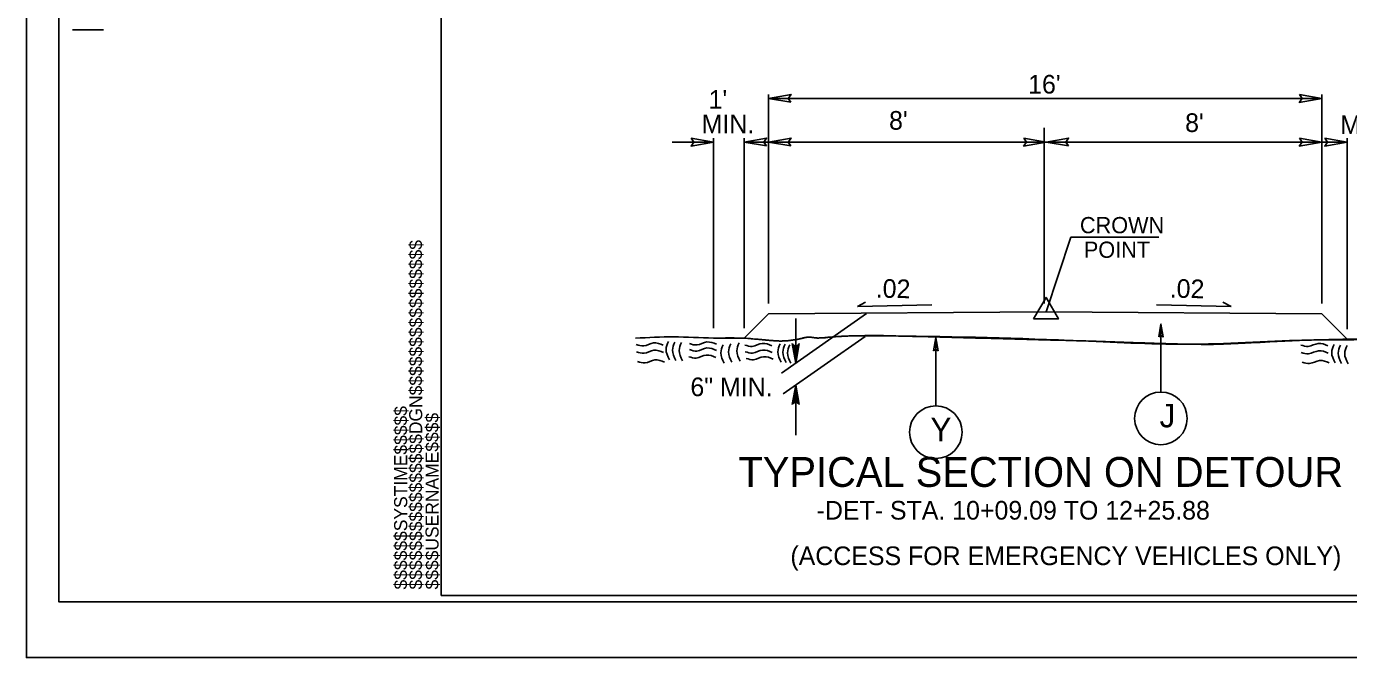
# Model space of a CAD drawing. Extents: x 575722 to 576066, y -53107 to -52774.
# Drawn here: x 575797.4 to 575850.6, y -53106.9 to -53081.5 of the extents above; entities that cross this region are included whole.
import ezdxf

# ---------------------------------------------------------------- set-up
doc = ezdxf.new("R2010")
doc.units = 0
for name, color, linetype in [('Old_Level_1', 7, 'Continuous'), ('Old_Level_11', 7, 'Continuous'), ('Old_Level_2', 7, 'Continuous'), ('Prop DSN Text', 7, 'Continuous'), ('Prop ROW Marker CELL', 7, 'Continuous'), ('Sheet Cutting Line CELL', 7, 'Continuous'), ('Sheet Plot Border Inside CELL', 7, 'Continuous'), ('Sheet Plot Border Outside CELL', 7, 'Continuous'), ('Sheet Typical CELL', 7, 'Continuous'), ('Typical Grade Point Symbol CELL', 7, 'Continuous'), ('Typical ID Circle CELL', 7, 'Continuous'), ('Typical Pavement Slope CELL', 7, 'Continuous'), ('Typical Terminator CELL', 7, 'Continuous'), ('Typical Text Grade Point CELL', 7, 'Continuous'), ('Typical Text ID Circle CELL', 7, 'Continuous')]:
    doc.layers.add(name, color=color, linetype=linetype)

msp = doc.modelspace()

# ---------------------------------------------------------------- linework, layer by layer
at = {"layer": 'Old_Level_11'}
for p, q in [((575827.258, -53092.635), (575827.258, -53084.22)), ((575849.531, -53092.635), (575849.531, -53084.22)), ((575849.531, -53084.38), (575827.258, -53084.38)), ((575838.357, -53092.635), (575838.357, -53085.564)), ((575825.044, -53086.137), (575823.379, -53086.137)), ((575825.044, -53093.617), (575825.044, -53085.977)), ((575826.273, -53093.624), (575826.273, -53085.977)), ((575827.258, -53086.137), (575826.273, -53086.137)), ((575838.357, -53086.137), (575827.258, -53086.137)), ((575849.531, -53086.137), (575838.357, -53086.137)), ((575850.555, -53086.137), (575849.531, -53086.137)), ((575850.555, -53093.663), (575850.555, -53085.977))]:
    msp.add_line(p, q, dxfattribs=at)
for points in [[(575828.158, -53084.535), (575827.258, -53084.38), (575828.163, -53084.22), (575828.048, -53084.38)], [(575848.631, -53084.225), (575849.531, -53084.38), (575848.626, -53084.54), (575848.741, -53084.38)], [(575824.144, -53085.982), (575825.044, -53086.137), (575824.139, -53086.297), (575824.254, -53086.137)], [(575827.173, -53086.292), (575826.273, -53086.137), (575827.178, -53085.977), (575827.063, -53086.137)], [(575828.158, -53086.292), (575827.258, -53086.137), (575828.163, -53085.977), (575828.048, -53086.137)], [(575837.531, -53085.982), (575838.431, -53086.137), (575837.526, -53086.297), (575837.641, -53086.137)], [(575839.331, -53086.292), (575838.431, -53086.137), (575839.336, -53085.977), (575839.221, -53086.137)], [(575848.631, -53085.982), (575849.531, -53086.137), (575848.626, -53086.297), (575848.741, -53086.137)], [(575849.655, -53085.982), (575850.555, -53086.137), (575849.65, -53086.297), (575849.765, -53086.137)]]:
    msp.add_lwpolyline(points, close=True, dxfattribs=at)
at = {"layer": 'Old_Level_2'}
for points in [[(575855.112, -53093.968), (575854.703, -53093.989), (575853.632, -53093.941), (575852.526, -53094.014), (575849.124, -53094.098), (575844.384, -53094.267), (575839.88, -53094.132), (575832.25, -53093.93), (575830.77, -53093.928), (575830.012, -53093.961), (575829.277, -53094.016), (575829.167, -53094.013), (575829.057, -53093.998), (575828.948, -53093.984), (575828.838, -53093.983), (575828.716, -53094.002), (575828.596, -53094.03), (575828.476, -53094.06), (575828.355, -53094.082), (575827.8, -53094.137), (575827.68, -53094.137), (575827.26, -53094.109), (575826.84, -53094.068), (575826, -53094.017), (575825.044, -53094.017), (575823.437, -53093.971), (575821.903, -53094.025)], [(575823.019, -53094.306), (575822.629, -53094.212), (575822.226, -53094.333), (575821.93, -53094.279)], [(575823.227, -53094.152), (575823.133, -53094.474), (575823.268, -53094.891)], [(575823.483, -53094.178), (575823.389, -53094.501), (575823.523, -53094.918)], [(575823.752, -53094.192), (575823.657, -53094.514), (575823.792, -53094.931)], [(575825.169, -53094.27), (575824.78, -53094.176), (575824.376, -53094.297), (575824.081, -53094.243)], [(575825.43, -53094.29), (575825.336, -53094.613), (575825.47, -53095.03)], [(575825.739, -53094.25), (575825.645, -53094.572), (575825.78, -53094.989)], [(575826.075, -53094.21), (575825.981, -53094.532), (575826.116, -53094.949)], [(575827.395, -53094.325), (575827.005, -53094.231), (575826.602, -53094.352), (575826.306, -53094.298)], [(575827.724, -53094.249), (575827.63, -53094.572), (575827.765, -53094.989)], [(575827.926, -53094.263), (575827.832, -53094.585), (575827.966, -53095.002)], [(575828.114, -53094.29), (575828.02, -53094.612), (575828.154, -53095.029)], [(575849.781, -53094.328), (575849.392, -53094.234), (575848.988, -53094.355), (575848.693, -53094.301)], [(575850.027, -53094.274), (575849.933, -53094.596), (575850.068, -53095.013)], [(575850.283, -53094.301), (575850.189, -53094.623), (575850.323, -53095.04)], [(575850.552, -53094.314), (575850.457, -53094.637), (575850.592, -53095.054)], [(575823.032, -53094.602), (575822.643, -53094.508), (575822.239, -53094.629), (575821.944, -53094.575)], [(575825.142, -53094.794), (575824.753, -53094.7), (575824.35, -53094.821), (575824.054, -53094.767)], [(575825.169, -53094.512), (575824.78, -53094.418), (575824.376, -53094.539), (575824.081, -53094.485)], [(575827.408, -53094.594), (575827.018, -53094.5), (575826.615, -53094.621), (575826.319, -53094.567)], [(575827.448, -53094.863), (575827.059, -53094.769), (575826.655, -53094.889), (575826.36, -53094.836)], [(575849.795, -53094.624), (575849.405, -53094.53), (575849.002, -53094.651), (575848.706, -53094.597)], [(575823.073, -53094.992), (575822.683, -53094.898), (575822.28, -53095.019), (575821.984, -53094.965)], [(575849.835, -53095.014), (575849.445, -53094.92), (575849.042, -53095.041), (575848.746, -53094.987)]]:
    msp.add_spline(points, degree=3, dxfattribs=at)
at = {"layer": 'Prop DSN Text'}
for p, q in [((575831.198, -53093.035), (575827.78, -53095.429)), ((575828.353, -53093.233), (575828.353, -53095.028)), ((575831.146, -53093.951), (575827.845, -53096.263)), ((575828.353, -53095.028), (575828.214, -53094.241)), ((575828.353, -53095.028), (575828.234, -53094.256)), ((575828.253, -53094.271), (575828.353, -53095.028)), ((575828.353, -53095.028), (575828.273, -53094.284)), ((575828.294, -53094.299), (575828.353, -53095.028)), ((575828.353, -53095.028), (575828.313, -53094.314)), ((575828.333, -53094.329), (575828.353, -53095.028)), ((575828.353, -53095.028), (575828.493, -53094.241)), ((575828.473, -53094.256), (575828.353, -53095.028)), ((575828.353, -53095.028), (575828.451, -53094.271)), ((575828.431, -53094.284), (575828.353, -53095.028)), ((575828.353, -53095.028), (575828.412, -53094.299)), ((575828.392, -53094.314), (575828.353, -53095.028)), ((575828.353, -53095.028), (575828.372, -53094.329)), ((575828.353, -53094.343), (575828.353, -53095.028)), ((575828.353, -53095.908), (575828.214, -53096.695)), ((575828.234, -53096.68), (575828.353, -53095.908)), ((575828.353, -53095.908), (575828.253, -53096.666)), ((575828.273, -53096.65), (575828.353, -53095.908)), ((575828.353, -53095.908), (575828.294, -53096.636)), ((575828.313, -53096.623), (575828.353, -53095.908)), ((575828.353, -53095.908), (575828.333, -53096.608)), ((575828.353, -53095.908), (575828.353, -53097.929)), ((575828.353, -53095.908), (575828.493, -53096.695)), ((575828.353, -53096.593), (575828.353, -53095.908)), ((575828.372, -53096.608), (575828.353, -53095.908)), ((575828.353, -53095.908), (575828.392, -53096.623)), ((575828.412, -53096.636), (575828.353, -53095.908)), ((575828.353, -53095.908), (575828.431, -53096.65)), ((575828.451, -53096.666), (575828.353, -53095.908)), ((575828.353, -53095.908), (575828.473, -53096.68))]:
    msp.add_line(p, q, dxfattribs=at)
msp.add_open_spline([(575851.784, -53094.032), (575850.897, -53094.054), (575850.01, -53094.076), (575849.124, -53094.098), (575848.729, -53094.108), (575848.334, -53094.127), (575847.939, -53094.144), (575847.544, -53094.161), (575847.149, -53094.187), (575846.754, -53094.205), (575845.964, -53094.242), (575845.174, -53094.279), (575844.384, -53094.267), (575843.634, -53094.255), (575842.883, -53094.231), (575842.132, -53094.207), (575841.381, -53094.182), (575840.631, -53094.153), (575839.88, -53094.132), (575838.609, -53094.096), (575837.337, -53094.063), (575836.065, -53094.029), (575834.793, -53093.994), (575833.522, -53093.962), (575832.25, -53093.93), (575831.757, -53093.918), (575831.263, -53093.919), (575830.77, -53093.928), (575830.517, -53093.933), (575830.265, -53093.948), (575830.012, -53093.961), (575829.767, -53093.974), (575829.522, -53094.004), (575829.277, -53094.016), (575829.24, -53094.018), (575829.204, -53094.017), (575829.167, -53094.013), (575829.131, -53094.008), (575829.094, -53094.003), (575829.057, -53093.998), (575829.021, -53093.993), (575828.984, -53093.988), (575828.948, -53093.984), (575828.911, -53093.98), (575828.874, -53093.98), (575828.838, -53093.983), (575828.797, -53093.987), (575828.756, -53093.993), (575828.716, -53094.002), (575828.676, -53094.011), (575828.636, -53094.021), (575828.596, -53094.03), (575828.556, -53094.04), (575828.516, -53094.05), (575828.476, -53094.06), (575828.436, -53094.069), (575828.396, -53094.076), (575828.355, -53094.082), (575828.171, -53094.11), (575827.986, -53094.129), (575827.8, -53094.137), (575827.76, -53094.139), (575827.72, -53094.139), (575827.68, -53094.137), (575827.54, -53094.13), (575827.4, -53094.121), (575827.26, -53094.109), (575827.12, -53094.096), (575826.981, -53094.08), (575826.84, -53094.068), (575826.561, -53094.045), (575826.281, -53094.017), (575826, -53094.017), (575825.681, -53094.017), (575825.362, -53094.017), (575825.044, -53094.017)], degree=3, dxfattribs=at)
at = {"layer": 'Prop ROW Marker CELL'}
msp.add_line((575838.431, -53092.959), (575838.431, -53092.959), dxfattribs=at)
msp.add_lwpolyline([(575837.931, -53093.247), (575838.431, -53092.383), (575838.931, -53093.247)], close=True, dxfattribs=at)
at = {"layer": 'Sheet Cutting Line CELL'}
for p, q in [((575797.38, -52996.867), (575797.38, -53106.867)), ((575797.38, -53106.867), (575965.78, -53106.867))]:
    msp.add_line(p, q, dxfattribs=at)
at = {"layer": 'Sheet Plot Border Inside CELL'}
msp.add_lwpolyline([(575965.33, -52999.112), (575798.68, -52999.112), (575798.68, -53104.622), (575965.33, -53104.622)], close=True, dxfattribs=at)
at = {"layer": 'Sheet Plot Border Outside CELL'}
msp.add_lwpolyline([(575965.78, -52996.867), (575797.38, -52996.867), (575797.38, -53106.867), (575965.78, -53106.867)], close=True, dxfattribs=at)
at = {"layer": 'Sheet Typical CELL'}
for p, q in [((575799.23, -53081.617), (575800.48, -53081.617)), ((575814.08, -53104.367), (575814.08, -53104.367)), ((575814.08, -53104.367), (575814.08, -53104.367)), ((575814.08, -53104.367), (575814.08, -53104.367)), ((575814.08, -53104.367), (575814.08, -53104.367)), ((575814.08, -53104.367), (575814.08, -53104.367)), ((575814.08, -53104.367), (575814.08, -53104.367))]:
    msp.add_line(p, q, dxfattribs=at)
msp.add_lwpolyline([(575964.08, -52999.367), (575814.08, -52999.367), (575814.08, -53104.367), (575964.08, -53104.367)], close=True, dxfattribs=at)
msp.add_lwpolyline([(575817.83, -53104.367), (575817.83, -53104.367)], dxfattribs=at)
at = {"layer": 'Typical Grade Point Symbol CELL'}
msp.add_line((575838.431, -53092.959), (575839.431, -53089.959), dxfattribs=at)
at = {"layer": 'Typical ID Circle CELL'}
for p, q in [((575843.054, -53096.19), (575843.054, -53093.456)), ((575833.994, -53096.746), (575833.994, -53094.012))]:
    msp.add_line(p, q, dxfattribs=at)
for centre in [(575843.054, -53097.248), (575833.994, -53097.804)]:
    msp.add_circle(centre, 1.058, dxfattribs=at)
at = {"layer": 'Typical Pavement Slope CELL'}
for p, q in [((575830.834, -53092.744), (575831.167, -53092.578)), ((575833.834, -53092.682), (575830.834, -53092.744)), ((575842.881, -53092.681), (575845.881, -53092.744)), ((575845.881, -53092.744), (575845.548, -53092.577)), ((575827.258, -53093.039), (575826.273, -53094.024)), ((575849.531, -53093.039), (575850.555, -53094.063))]:
    msp.add_line(p, q, dxfattribs=at)
msp.add_lwpolyline([(575827.258, -53093.039), (575838.431, -53092.959), (575849.531, -53093.039)], dxfattribs=at)
at = {"layer": 'Typical Terminator CELL'}
for points in [[(575842.966, -53093.972), (575843.054, -53093.456), (575843.146, -53093.975), (575843.054, -53093.909)], [(575833.905, -53094.528), (575833.994, -53094.012), (575834.086, -53094.531), (575833.994, -53094.465)]]:
    msp.add_lwpolyline(points, close=True, dxfattribs=at)
at = {"layer": 'Typical Text Grade Point CELL'}
msp.add_line((575839.431, -53089.959), (575842.969, -53089.959), dxfattribs=at)

# ---------------------------------------------------------------- texts
at = {"layer": 'Old_Level_1'}
for p in [(575831.568, -53092.389), (575843.404, -53092.391)]:
    msp.add_text('.02', height=0.75, rotation=358.8084, dxfattribs=at).set_placement(p)
at = {"layer": 'Old_Level_11'}
for s, p in [("16'", (575837.71, -53084.185)), (" 1'", (575824.566, -53084.797)), ('MIN.', (575824.566, -53085.78)), ("8'", (575832.11, -53085.639)), ("8'", (575844.03, -53085.731)), ('MIN.', (575850.273, -53085.816))]:
    msp.add_text(s, height=0.75, rotation=360, dxfattribs=at).set_placement(p)
at = {"layer": 'Prop DSN Text'}
for s, p in [('6" MIN.', (575824.112, -53096.356)), ('-DET- STA. 10+09.09 TO 12+25.88', (575829.194, -53101.319)), ('(ACCESS FOR EMERGENCY VEHICLES ONLY)', (575828.138, -53103.15))]:
    msp.add_text(s, height=0.75, dxfattribs=at).set_placement(p)
at = {"layer": 'Sheet Typical CELL'}
for s, p in [('$$$$$$$$$$$$$$$$DGN$$$$$$$$$$$$$$$$', (575813.315, -53104.13)), ('$$$$$$SYSTIME$$$$$', (575812.71, -53104.13)), ('$$$$USERNAME$$$$', (575813.973, -53104.129))]:
    msp.add_text(s, height=0.525, rotation=90, dxfattribs=at).set_placement(p)
at = {"layer": 'Typical Pavement Slope CELL'}
msp.add_text('TYPICAL SECTION ON DETOUR', height=1.2, dxfattribs=at).set_placement((575826.049, -53100.003))
at = {"layer": 'Typical Text Grade Point CELL'}
for s, p in [('CROWN', (575839.795, -53089.803)), ('POINT', (575839.953, -53090.791))]:
    msp.add_text(s, height=0.6525, dxfattribs=at).set_placement(p)
at = {"layer": 'Typical Text ID Circle CELL'}
for s, height, p in [('J ', 0.9469, (575843.003, -53097.611)), ('Y', 0.947, (575833.777, -53098.166))]:
    msp.add_text(s, height=height, dxfattribs=at).set_placement(p)

doc.saveas('drawing.dxf')
